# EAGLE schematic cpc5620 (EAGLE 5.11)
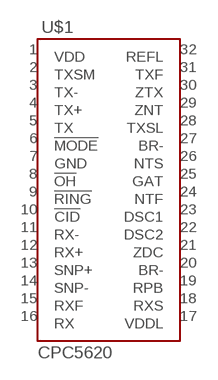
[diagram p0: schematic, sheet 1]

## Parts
U$1  CPC5620  [SOIC-32]
Unconnected: U$1.1(VDD) U$1.2(TXSM) U$1.3(TX-) U$1.4(TX+) U$1.5(TX) U$1.6(!MODE) U$1.7(GND) U$1.8(!OH) U$1.9(!RING) U$1.10(!CID) U$1.11(RX-) U$1.12(RX+) U$1.13(SNP+) U$1.14(SNP-) U$1.15(RXF) U$1.16(RX) U$1.17(VDDL) U$1.18(RXS) U$1.19(RPB) U$1.20(BR-) U$1.21(ZDC) U$1.22(DSC2) U$1.23(DSC1) U$1.24(NTF) U$1.25(GAT) U$1.26(NTS) U$1.27(BR-) U$1.28(TXSL) U$1.29(ZNT) U$1.30(ZTX) U$1.31(TXF) U$1.32(REFL)

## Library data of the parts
U$1 = trl:CPC5620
